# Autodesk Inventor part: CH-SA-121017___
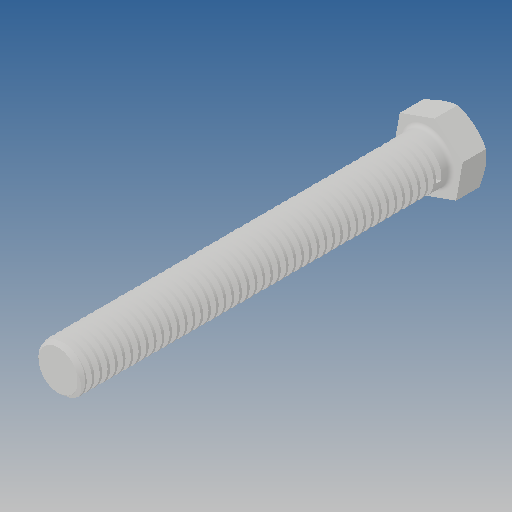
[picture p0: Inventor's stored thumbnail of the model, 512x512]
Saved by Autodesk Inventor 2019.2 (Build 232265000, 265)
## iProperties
Created: 2010-06
Part Number: CH-SA-121017___
Material: Ogólny
Document SubType Name: Modeling
Designer: CADENGINEERING4
Density: 1 g/cm^3
Appearance: Domyślna
Author: CADENGINEERING4
Revision Number: ANY
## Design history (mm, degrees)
feature "NONE"
node "Bryła1"
